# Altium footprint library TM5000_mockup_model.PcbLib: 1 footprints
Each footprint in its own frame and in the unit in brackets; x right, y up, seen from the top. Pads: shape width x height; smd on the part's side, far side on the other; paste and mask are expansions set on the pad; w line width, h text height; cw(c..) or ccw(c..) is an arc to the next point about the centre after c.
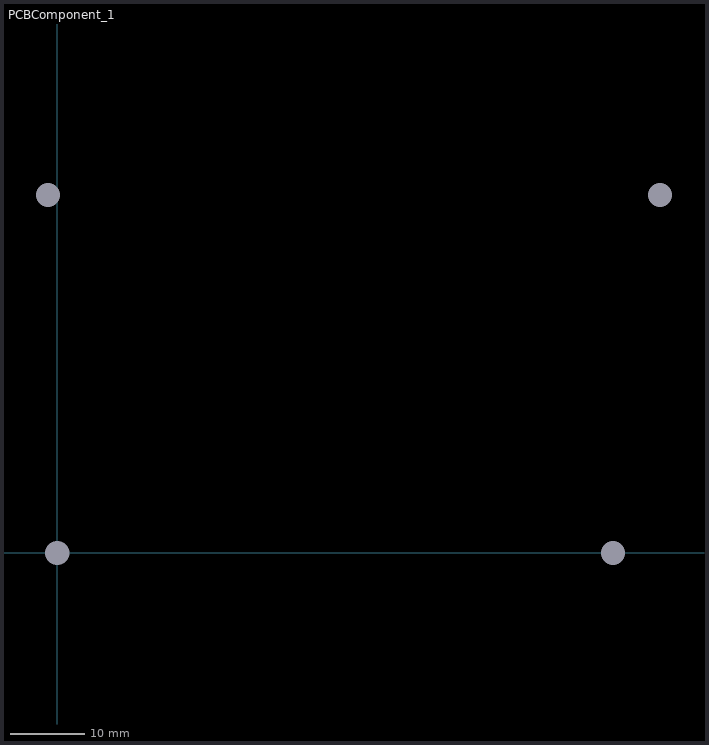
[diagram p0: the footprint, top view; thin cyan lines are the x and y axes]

## PCBComponent_1 [mil]
pads (4):
  round 0 hole 128: 1(-50,1900) 1(0,0) 1(2950,0) 1(3200,1900)
3D body: height 511.81, standoff 440.94, extent -964.57,-708.66 4311.02,2814.96
3D body: height 440.94, standoff 283.46, extent -649.61,-492.13 4114.17,2460.63
3D body: height 236.22, standoff 0, extent -148.42,1801.71 48.43,1998.3
3D body: height 236.22, standoff 0, extent 3101.58,1801.71 3298.43,1998.31
3D body: height 236.22, standoff 0, extent -98.42,-98.29 98.43,98.3
3D body: height 236.22, standoff 0, extent 2851.58,-98.29 3048.43,98.3
3D body: height 267.72, standoff 236.22, extent -314.96,-157.48 3366.14,2244.09
3D body: height 267.72, standoff 236.22, extent -1240.16,118.11 -314.96,2125.98
3D body: height 269.69, standoff 267.72, extent -954.72,1584.78 -639.76,1899.48
3D body: height 269.69, standoff 267.72, extent -954.72,1171.4 -639.76,1486.1
3D body: height 269.69, standoff 267.72, extent -954.72,758.01 -639.76,1072.71
3D body: height 269.69, standoff 267.72, extent -954.72,354.46 -639.76,669.17
3D body: height 236.22, standoff 196.85, extent 669.29,1574.8 669.29,1574.8
3D body: height 236.22, standoff 196.85, extent 1870.08,1673.23 3059.06,1781.5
